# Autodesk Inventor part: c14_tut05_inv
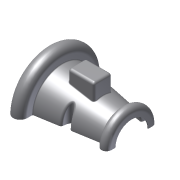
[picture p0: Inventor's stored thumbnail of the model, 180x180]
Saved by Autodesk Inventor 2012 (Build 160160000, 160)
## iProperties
Created: 2010-04
Part Number: c14_tut05_inv
Document SubType Name: Modeling
Designer: CADSoft
Density: 1 g/cm^3
Material: Default
Author: CADSoft
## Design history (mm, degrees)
sketch "Sketch1"
  geometry: L1 (-50, 30)-(-50, 42.5); L2 (-35, 42.5)-(-35, 35); L3 (-35, 35)-(40, 22.5); L4 (40, 22.5)-(40, 25); L5 (50, 25)-(50, 20); L6 (-45.581, 0)-(8.786, 0); A1 r 7.5 centre (-42.5, 42.5) between (-35, 42.5) and (-50, 42.5); A2 r 5 centre (45, 25) between (50, 25) and (40, 25); 2 further points
  constraints: 12 end point, 4 point on circle, 4 tangent, 3 parallel, 2 centre point, 1 coincident, 1 perpendicular, 1 point on line, 1 vertical, 1 other
  dimensions: "d0" = 60 diameter of L1.start L6; "d1" = 85 diameter of L1.end L6; "d2" = 70 diameter of L2.end L6; "d3" = 40 diameter of L5.end L6; "d4" = 45 diameter of L3.end L6; "d5" = 50 diameter of L5.start L6; "d6" = 7.5 radius of A1; "d7" = 5 radius of A2; "d8" = 50 distance from line of L1 point (0, 0); "d9" = 100 distance between parallel lines of L5 L1
feature "RevolutionSrf1" sketch "Sketch1" dims angle "d10" = 180 deg
sketch "Sketch2" dims "d11" = 5, "d12" = 10
  geometry: L1 (-35, 35)-(40, 22.5) reference; L2 (50, -25)-(50, 25) reference; 2 further points; 1 other entity
  constraints: 1 point on line, 2 other
  dimensions: "d13" = 50 distance from line of L2 point (0, 29.167)
extrude_surface "ExtrusionSrf1" sketch "Sketch2" dims "d14" = 30, "d15" = 0
mirror "Mirror1"
feature "Trim1"
feature "Trim2"
feature "Trim3"
feature "Trim4"
workplane "Work Plane1"
sketch "Sketch3"
  geometry: L1 (-15, 10)-(15, 10); L2 (15, 10)-(15, -10); L3 (15, -10)-(-15, -10); L4 (-15, -10)-(-15, 10); 1 further point
  constraints: 8 end point, 2 parallel, 1 horizontal, 1 perpendicular
  dimensions: "d17" = 30 distance of L1.start L1.end; "d18" = 20 distance of L1.end L2.end; "d19" = 15 distance from line of L4 point (0, 0); "d20" = 10 distance from line of L3 point (0, 0)
split "Split1"
delete_face "Delete Face1"
feature "Stitch Surface1"
fillet "Fillet1" dims "d34" = 2
thicken "Thicken1" dims "d35" = 1
body "Solid2"
body "Srf1"
body "Srf2"
body "Srf3"
sketch "3D Sketch1"
  geometry: L1 through (0, 0) direction (1, 5.73e-16) reference; L2 through (0, 0) direction (-1, -5.73e-16) reference; 4 other entities
  constraints: 6 horizontal
body "Srf4"
body "Srf5"
body "Srf6"
extrude_surface "ExtrusionSrf2"
feature "LoftSrf1" dims "d25" = 0, "d26" = 90 deg, "d27" = 0, "d28" = 90 deg
patch "Boundary Patch1" dims "d29" = 0, "d30" = 0, "d31" = 0, "d32" = 0, "d33" = 0
other parameters: "d16" = 45
